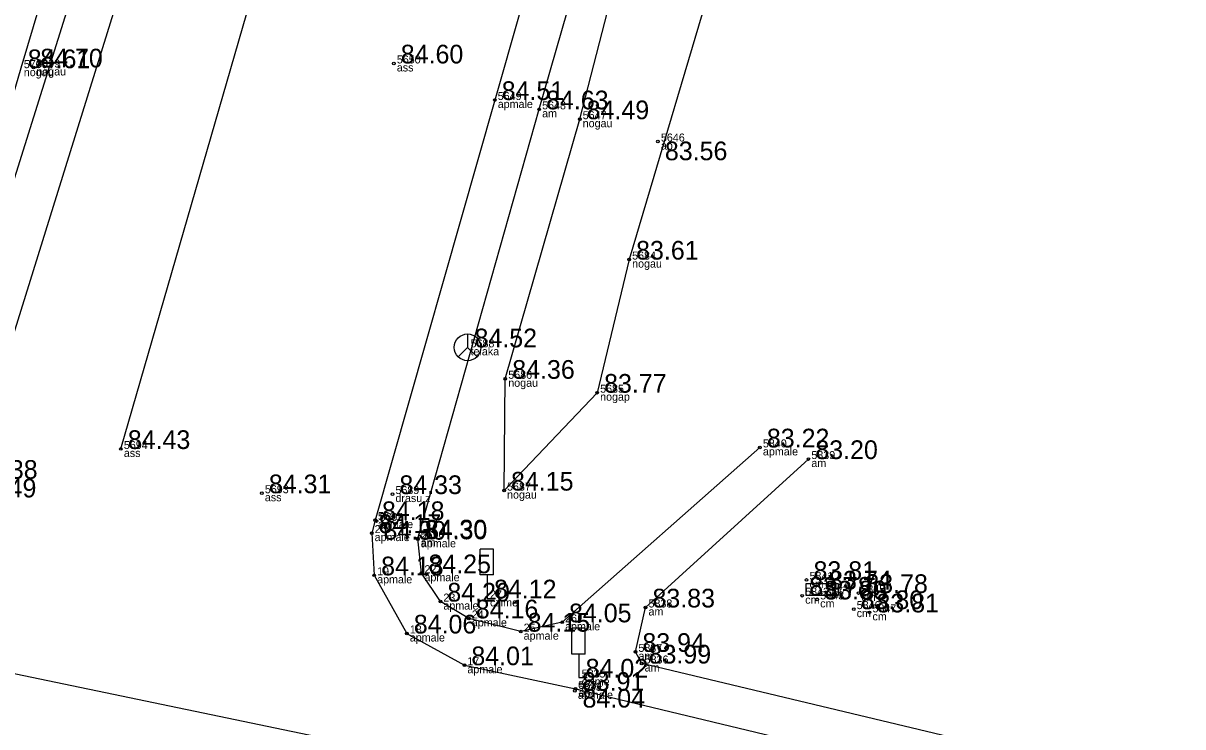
# Model space of a CAD drawing. Extents: x 614911 to 615803, y 262110 to 264311.
# Drawn here: x 615549.17 to 615592.62, y 262765.01 to 262791.37 of the extents above; entities that cross this region are included whole.
import ezdxf

# ---------------------------------------------------------------- set-up
doc = ezdxf.new("R2010")
doc.units = 0
for name, color, linetype in [('Level 16', 7, 'Continuous'), ('Level 18', 7, 'Continuous'), ('Level 31', 7, 'Continuous'), ('Level 37', 7, 'Continuous'), ('Level 49', 7, 'Continuous'), ('Level 53', 7, 'Continuous'), ('Level 54', 7, 'Continuous'), ('Level 57', 7, 'Continuous'), ('Level 58', 7, 'Continuous')]:
    doc.layers.add(name, color=color, linetype=linetype)

msp = doc.modelspace()

# ---------------------------------------------------------------- linework, layer by layer
at = {"layer": 'Level 16'}
for p, q in [((615566.797, 262771.668), (615566.297, 262771.668)), ((615566.297, 262770.699), (615566.297, 262771.668)), ((615566.797, 262770.699), (615566.797, 262771.668)), ((615566.797, 262770.699), (615566.297, 262770.699)), ((615566.551, 262770.699), (615566.551, 262769.821)), ((615566.551, 262769.821), (615566.866, 262769.821)), ((615570.231, 262768.704), (615569.731, 262768.704)), ((615569.731, 262767.735), (615569.731, 262768.704)), ((615570.231, 262767.735), (615570.231, 262768.704)), ((615570.231, 262767.735), (615569.731, 262767.735)), ((615569.985, 262767.735), (615569.985, 262766.857)), ((615569.985, 262766.857), (615570.3, 262766.857))]:
    msp.add_line(p, q, dxfattribs=at)
at = {"layer": 'Level 18'}
msp.add_lwpolyline([(615578.51, 262770.38), (615579.71, 262770.38), (615579.71, 262769.93), (615578.51, 262769.93)], close=True, dxfattribs=at)
at = {"layer": 'Level 31'}
for points in [[(615556.487, 262814.508), (615549.081, 262789.685), (615544.759, 262774.905), (615542.417, 262774.44)], [(615567.19, 262773.86), (615567.235, 262778.049), (615570.024, 262787.772), (615574.951, 262806.875), (615575.977, 262809.733)], [(615579.524, 262805.902), (615575.261, 262793.923), (615571.876, 262782.514), (615570.677, 262777.527), (615567.19, 262773.86)]]:
    msp.add_lwpolyline(points, dxfattribs=at)
at = {"layer": 'Level 37'}
for points in [[(615629.654, 263149.948), (615628.721, 263134.164), (615628.583, 263132.388), (615627.854, 263104.61), (615621.91, 263025.585), (615621.904, 263025.311), (615619.521, 263012.239), (615619.398, 263011.725), (615613.627, 262992.503), (615605.986, 262968.61), (615598.735, 262946.405), (615591.778, 262924.107), (615585.103, 262902.604), (615578.685, 262882.008), (615572.188, 262861.032), (615562.921, 262830.982), (615557.662, 262813.841), (615551.445, 262793.883), (615545.378, 262774.577), (615544.847, 262773.643)], [(615552.83, 262775.419), (615557.688, 262792.217), (615564.381, 262810.929), (615568.874, 262829.598), (615578.474, 262860.105), (615584.765, 262880.506), (615591.133, 262901.009), (615597.793, 262922.52), (615604.506, 262944.221), (615611.821, 262967.016), (615619.311, 262990.31), (615624.144, 263005.661), (615628.856, 263023.992)], [(615633.153, 262995.478), (615630.105, 262994.778), (615627.249, 262993.097), (615624.165, 262989.775), (615623.012, 262986.721), (615615.941, 262964.659), (615608.941, 262942.572), (615602.23, 262921.018), (615595.493, 262899.514), (615589.041, 262878.574), (615583.023, 262859.136), (615579.804, 262848.845), (615577.579, 262826.156), (615572.51, 262808.384), (615566.84, 262788.492), (615562.353, 262772.755), (615562.228, 262772.268), (615562.322, 262770.686), (615563.546, 262768.507), (615565.703, 262767.319), (615569.868, 262766.432), (615584.992, 262762.796)], [(615615.254, 262992.037), (615607.495, 262968.204), (615600.361, 262945.823), (615593.41, 262923.721), (615586.741, 262902.064), (615580.351, 262881.537), (615573.832, 262860.567), (615564.576, 262830.529), (615559.267, 262813.314), (615553.068, 262793.425), (615547.108, 262774.302), (615545.744, 262772.518), (615544.641, 262771.987), (615542.393, 262772.794), (615538.581, 262772.6), (615523.132, 262777.208), (615510.602, 262781.905), (615510.241, 262783.659)], [(615576.777, 262775.478), (615569.363, 262768.926), (615567.812, 262768.576), (615565.869, 262769.072), (615564.804, 262769.703), (615564.095, 262770.764), (615563.953, 262772.067), (615568.503, 262788.143), (615574.022, 262807.322), (615574.429, 262808.778), (615575.157, 262809.439)], [(615505.593, 262781.081), (615537.899, 262769.283), (615568.986, 262762.814), (615584.198, 262759.491)], [(615585.272, 262764.3), (615572.345, 262767.383), (615572.113, 262767.818), (615572.49, 262769.482), (615578.592, 262775.042)]]:
    msp.add_lwpolyline(points, dxfattribs=at)
at = {"layer": 'Level 49'}
msp.add_line((615565.822, 262779.227), (615566.176, 262778.873), dxfattribs=at)
msp.add_lwpolyline([(615565.822, 262779.727), (615565.822, 262779.227), (615565.468, 262778.873)], dxfattribs=at)
msp.add_circle((615565.822, 262779.227), 0.5, dxfattribs=at)
at = {"layer": 'Level 57'}
for centre in [(615563.059, 262789.862), (615549.55, 262789.712), (615566.84, 262788.492), (615568.503, 262788.143), (615570.024, 262787.772), (615572.955, 262786.936), (615571.876, 262782.514), (615567.235, 262778.049), (615570.677, 262777.527), (615552.83, 262775.419), (615576.777, 262775.478), (615578.592, 262775.042), (615567.19, 262773.86), (615558.114, 262773.761), (615563.007, 262773.73), (615562.353, 262772.755), (615562.41, 262772.721), (615562.228, 262772.268), (615563.953, 262772.067), (615563.96, 262772.037), (615564.095, 262770.764), (615562.322, 262770.686), (615578.525, 262770.512), (615578.362, 262769.922), (615580.466, 262770.023), (615564.804, 262769.703), (615572.49, 262769.482), (615578.924, 262769.783), (615565.869, 262769.072), (615580.291, 262769.419), (615580.883, 262769.298), (615567.812, 262768.576), (615569.363, 262768.926), (615563.546, 262768.507), (615572.113, 262767.818), (615565.703, 262767.319), (615572.345, 262767.383), (615569.868, 262766.432), (615569.843, 262766.36)]:
    msp.add_circle(centre, 0.05, dxfattribs=at)
at = {"layer": 'Level 58'}
for centre in [(615563.059, 262789.862), (615549.55, 262789.712), (615566.84, 262788.492), (615568.503, 262788.143), (615570.024, 262787.772), (615572.955, 262786.936), (615571.876, 262782.514), (615567.235, 262778.049), (615570.677, 262777.527), (615552.83, 262775.419), (615576.777, 262775.478), (615578.592, 262775.042), (615567.19, 262773.86), (615558.114, 262773.761), (615563.007, 262773.73), (615562.353, 262772.755), (615562.41, 262772.721), (615562.228, 262772.268), (615563.953, 262772.067), (615563.96, 262772.037), (615564.095, 262770.764), (615562.322, 262770.686), (615578.525, 262770.512), (615578.362, 262769.922), (615580.466, 262770.023), (615564.804, 262769.703), (615572.49, 262769.482), (615578.924, 262769.783), (615565.869, 262769.072), (615580.291, 262769.419), (615580.883, 262769.298), (615567.812, 262768.576), (615569.363, 262768.926), (615563.546, 262768.507), (615572.113, 262767.818), (615565.703, 262767.319), (615572.345, 262767.383), (615569.868, 262766.432), (615569.843, 262766.36)]:
    msp.add_circle(centre, 0.05, dxfattribs=at)

# ---------------------------------------------------------------- texts
at = {"layer": 'Level 49'}
msp.add_text(' 84.52', height=0.7, dxfattribs=at).set_placement((615565.822, 262779.227))
at = {"layer": 'Level 53'}
for s, p in [(' nogau', (615549.081, 262789.385)), (' nogau', (615549.55, 262789.412)), (' ass', (615563.059, 262789.562)), (' apmale', (615566.84, 262788.192)), (' am', (615568.503, 262787.843)), (' nogau', (615570.024, 262787.472)), (' ap', (615572.955, 262786.636)), (' nogau', (615571.876, 262782.214)), (' telaka', (615565.822, 262778.927)), (' nogau', (615567.235, 262777.749)), (' nogap', (615570.677, 262777.227)), (' ass', (615552.83, 262775.119)), (' apmale', (615576.777, 262775.178)), (' am', (615578.592, 262774.742)), (' ass', (615558.114, 262773.461)), (' drasu.z', (615563.007, 262773.43)), (' nogau', (615567.19, 262773.56)), (' apmale', (615562.353, 262772.455)), (' ap', (615562.41, 262772.421)), (' apmale', (615562.228, 262771.968)), (' am', (615563.953, 262771.767)), (' apmale', (615563.96, 262771.737)), (' apmale', (615562.322, 262770.386)), (' apmale', (615564.095, 262770.464)), (' cm', (615578.525, 262770.212)), (' elsk', (615579.11, 262769.855)), (' cm', (615580.466, 262769.723)), (' apmale', (615564.804, 262769.403)), (' czime', (615566.551, 262769.521)), (' cm', (615578.362, 262769.622)), (' cm', (615578.924, 262769.483)), (' apmale', (615565.869, 262768.772)), (' am', (615572.49, 262769.182)), (' cm', (615580.291, 262769.119)), (' cm', (615580.883, 262768.998)), (' apmale', (615569.363, 262768.626)), (' apmale', (615563.546, 262768.207)), (' apmale', (615567.812, 262768.276)), (' am', (615572.113, 262767.518)), (' apmale', (615565.703, 262767.019)), (' am', (615572.345, 262767.083)), (' czime', (615569.985, 262766.557)), (' apmale', (615569.843, 262766.06)), (' ap', (615569.868, 262766.132))]:
    msp.add_text(s, height=0.3, dxfattribs=at).set_placement(p)
at = {"layer": 'Level 54'}
for s, p in [(' 5700', (615549.081, 262789.685)), (' 8899', (615549.55, 262789.712)), (' 5650', (615563.059, 262789.862)), (' 5649', (615566.84, 262788.492)), (' 5648', (615568.503, 262788.143)), (' 5647', (615570.024, 262787.772)), (' 5646', (615572.955, 262786.936)), (' 5684', (615571.876, 262782.514)), (' 5688', (615565.822, 262779.227)), (' 5686', (615567.235, 262778.049)), (' 5685', (615570.677, 262777.527)), (' 5694', (615552.83, 262775.419)), (' 5840', (615576.777, 262775.478)), (' 5839', (615578.592, 262775.042)), (' 5693', (615558.114, 262773.761)), (' 5689', (615563.007, 262773.73)), (' 5687', (615567.19, 262773.86)), (' 5691', (615562.353, 262772.755)), (' 5692', (615562.41, 262772.721)), (' 20', (615562.228, 262772.268)), (' 5690', (615563.953, 262772.067)), (' 21', (615563.96, 262772.037)), (' 19', (615562.322, 262770.686)), (' 22', (615564.095, 262770.764)), (' 5841', (615578.525, 262770.512)), (' 5844', (615579.11, 262770.155)), (' 23', (615564.804, 262769.703)), (' 27', (615566.551, 262769.821)), (' 5842', (615578.362, 262769.922)), (' 5843', (615578.924, 262769.783)), (' 5845', (615580.466, 262770.023)), (' 5838', (615572.49, 262769.482)), (' 5846', (615580.291, 262769.419)), (' 5847', (615580.883, 262769.298)), (' 24', (615565.869, 262769.072)), (' 26', (615569.363, 262768.926)), (' 18', (615563.546, 262768.507)), (' 25', (615567.812, 262768.576)), (' 5837', (615572.113, 262767.818)), (' 17', (615565.703, 262767.319)), (' 5836', (615572.345, 262767.383)), (' 5835', (615569.985, 262766.857)), (' 5833', (615569.843, 262766.36)), (' 5834', (615569.868, 262766.432))]:
    msp.add_text(s, height=0.3, dxfattribs=at).set_placement(p)
at = {"layer": 'Level 58'}
for s, p in [(' 84.61', (615549.081, 262789.685)), (' 84.70', (615549.55, 262789.712)), (' 84.60', (615563.059, 262789.862)), (' 84.51', (615566.84, 262788.492)), (' 84.63', (615568.503, 262788.143)), (' 84.49', (615570.024, 262787.772)), (' 83.56', (615572.955, 262786.236)), (' 83.61', (615571.876, 262782.514)), (' 84.36', (615567.235, 262778.049)), (' 83.77', (615570.677, 262777.527)), (' 84.43', (615552.83, 262775.419)), (' 83.22', (615576.777, 262775.478)), (' 83.20', (615578.592, 262775.042)), (' 84.38', (615547.108, 262774.302)), (' 84.49', (615547.062, 262773.605)), (' 84.31', (615558.114, 262773.761)), (' 84.33', (615563.007, 262773.73)), (' 84.15', (615567.19, 262773.86)), (' 84.18', (615562.353, 262772.755)), (' 84.17', (615562.228, 262772.268)), (' 84.30', (615562.41, 262772.021)), (' 84.30', (615563.953, 262772.067)), (' 84.30', (615563.96, 262772.037)), (' 84.13', (615562.322, 262770.686)), (' 84.25', (615564.095, 262770.764)), (' 83.81', (615578.525, 262770.512)), (' 83.74', (615579.11, 262770.155)), (' 84.20', (615564.804, 262769.703)), (' 84.12', (615566.551, 262769.821)), (' 83.78', (615578.362, 262769.922)), (' 83.80', (615578.924, 262769.783)), (' 83.78', (615580.466, 262770.023)), (' 83.83', (615572.49, 262769.482)), (' 83.80', (615580.291, 262769.419)), (' 83.81', (615580.883, 262769.298)), (' 84.16', (615565.869, 262769.072)), (' 84.05', (615569.363, 262768.926)), (' 84.06', (615563.546, 262768.507)), (' 84.15', (615567.812, 262768.576)), (' 83.94', (615572.113, 262767.818)), (' 84.01', (615565.703, 262767.319)), (' 83.99', (615572.345, 262767.383)), (' 84.02', (615569.985, 262766.857)), (' 83.91', (615569.843, 262766.36)), (' 84.04', (615569.868, 262765.732))]:
    msp.add_text(s, height=0.7, dxfattribs=at).set_placement(p)

doc.saveas('drawing.dxf')
